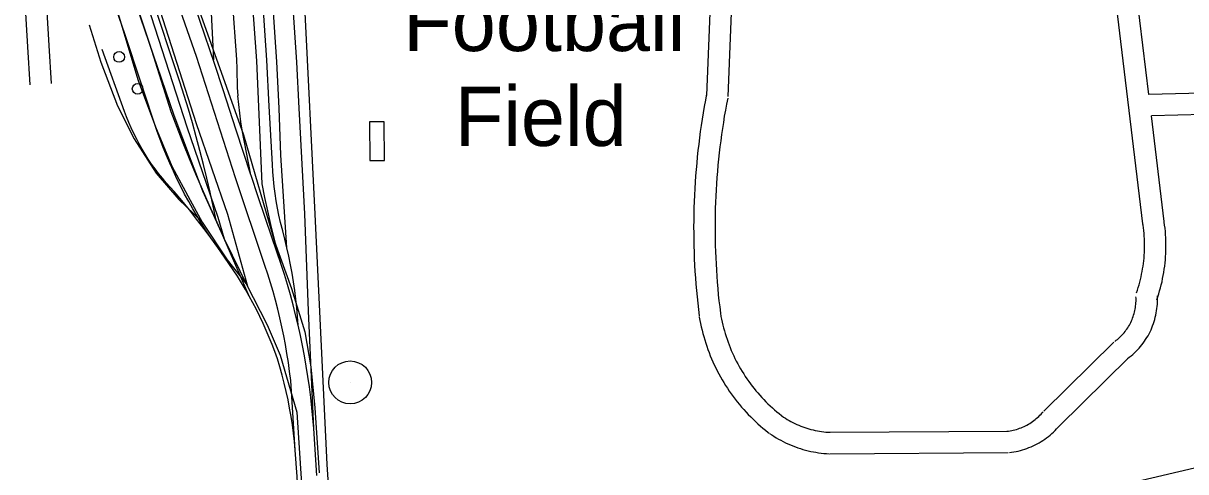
# Model space of a CAD drawing. Extents: x 3313447 to 3351316, y 703786 to 729172.
# Drawn here: x 3330404 to 3332031, y 712016 to 712643 of the extents above; entities that cross this region are included whole.
import ezdxf

# ---------------------------------------------------------------- set-up
doc = ezdxf.new("R2010")
doc.units = 0
for name, color, linetype in [('V-BLDG-IDEN', 7, 'Continuous'), ('V-BLDG-OTLN', 7, 'Continuous'), ('V-DOMW-TANK', 7, 'Continuous'), ('V-RAIL-TRAK', 7, 'Continuous'), ('V-ROAD-CNTR', 7, 'Continuous')]:
    doc.layers.add(name, color=color, linetype=linetype)

msp = doc.modelspace()

# ---------------------------------------------------------------- linework, layer by layer
at = {"layer": 'V-BLDG-OTLN'}
msp.add_lwpolyline([(3330908.9, 712505.4), (3330888.4, 712505.2), (3330888.9, 712451), (3330909.3, 712451.2)], close=True, dxfattribs=at)
at = {"layer": 'V-DOMW-TANK'}
msp.add_line((3330861.5, 712140.6), (3330861.5, 712140.6), dxfattribs=at)
for centre, radius in [((3330538, 712596.2), 7.6), ((3330563.9, 712551.5), 7.51), ((3330861.5, 712140.6), 30)]:
    msp.add_circle(centre, radius, dxfattribs=at)
at = {"layer": 'V-RAIL-TRAK'}
for p, q in [((3330738.2, 712418.4), (3330733.6, 712526.4)), ((3330752.7, 712445.7), (3330748, 712527.3)), ((3330751.8, 712344), (3330732.8, 712400.3)), ((3330720, 712261.5), (3330673.7, 712367.7)), ((3330764.9, 712305.5), (3330751.8, 712344)), ((3330769.4, 712291.5), (3330764.9, 712305.5)), ((3330810.6, 712076), (3330803, 712240.9))]:
    msp.add_line(p, q, dxfattribs=at)
for points in [[(3330555.1, 714786.3), (3330556.3, 714764.1), (3330562.7, 714620.4), (3330568.6, 714518.3), (3330575.8, 714388.5), (3330584.5, 714231), (3330594, 714085.6), (3330599, 713950), (3330607.6, 713814.8), (3330616.2, 713658.3), (3330624.9, 713507.5), (3330635.3, 713296.5), (3330670.1, 712592.1)], [(3330733.6, 712526.4), (3330730.6, 712590.9), (3330724.8, 712674), (3330720.4, 712758.3), (3330715.2, 712847.8), (3330709.8, 712944.5), (3330704.3, 713046.6), (3330700.3, 713123), (3330694.7, 713241.7)], [(3330748, 712527.3), (3330745, 712591.8), (3330739.2, 712674.9), (3330734.8, 712759.2), (3330729.6, 712848.7), (3330724.3, 712945.4), (3330718.8, 713047.5), (3330714.8, 713123.9), (3330709, 713238.6)], [(3330761.9, 712524.6), (3330758.9, 712589.1), (3330753.1, 712672.3), (3330748.7, 712756.5), (3330743.5, 712846), (3330738.2, 712942.7), (3330732.6, 713044.8), (3330728.7, 713121.2), (3330721.5, 713240.8)], [(3330789.9, 712524.5), (3330786.9, 712589), (3330781.1, 712672.1), (3330776.7, 712756.4), (3330771.6, 712845.9), (3330766.2, 712942.6), (3330760.7, 713044.7), (3330756.7, 713121.1), (3330750.5, 713241.7)], [(3330666.2, 713236.3), (3330672, 713124.8), (3330676, 713048.3), (3330681.5, 712946.3), (3330686.9, 712849.6), (3330692, 712760), (3330696.4, 712675.8), (3330702.2, 712592.7), (3330702.9, 712579.7)], [(3330673.7, 712367.7), (3330669.6, 712387.2), (3330665.3, 712406.8), (3330660.8, 712426.3), (3330656, 712445.7), (3330651.1, 712465.1), (3330645.9, 712484.4), (3330640.5, 712503.7), (3330634.9, 712522.9), (3330629.1, 712542.1), (3330623, 712561.1), (3330581.4, 712686.7), (3330537.1, 712816.2), (3330492.7, 712946.3), (3330429, 713159.4), (3330422.6, 713183.3)], [(3330673.7, 712367.7), (3330664, 712389), (3330654.5, 712410.4), (3330645.3, 712432), (3330636.3, 712453.6), (3330627.6, 712475.3), (3330619.1, 712497.2), (3330610.8, 712519.1), (3330581, 712613.9), (3330502.5, 712850.6), (3330464.1, 712962.8), (3330447.1, 713019.1), (3330441, 713043.5), (3330435.3, 713068), (3330429.8, 713092.5), (3330424.6, 713117.1)], [(3330666.5, 712342.8), (3330659.9, 712352.8), (3330653.5, 712362.9), (3330647.3, 712373.1), (3330641.2, 712383.4), (3330635.4, 712393.8), (3330629.7, 712404.3), (3330624.3, 712414.9), (3330619, 712425.6), (3330613.9, 712436.4), (3330609, 712447.3), (3330604.2, 712458.3), (3330599.7, 712469.3), (3330595.4, 712480.4), (3330591.3, 712491.6), (3330545.9, 712628.4), (3330474.3, 712836)], [(3330784.6, 712046), (3330778.2, 712143.2), (3330776.7, 712155.8), (3330774.9, 712168.4), (3330773, 712181), (3330770.9, 712193.5), (3330768.5, 712206), (3330765.9, 712218.5), (3330763.1, 712230.9), (3330760.2, 712243.3), (3330757, 712255.6), (3330753.6, 712267.9), (3330750, 712280.1), (3330746.1, 712292.2), (3330742.1, 712304.3), (3330701, 712427), (3330646.1, 712596.7), (3330576, 712798.2)], [(3330671.5, 712586.8), (3330651.5, 712645.7), (3330627.2, 712717)], [(3330691.7, 712307), (3330685.5, 712315.7), (3330676.1, 712329.4), (3330666.5, 712342.8), (3330656.6, 712356.1), (3330646.5, 712369.3), (3330636.3, 712382.3), (3330625.8, 712395.1), (3330615.1, 712407.8), (3330609.4, 712413.9), (3330603.9, 712420.1), (3330598.5, 712426.4), (3330593.3, 712432.9), (3330588.3, 712439.5), (3330583.5, 712446.3), (3330578.8, 712453.1), (3330574.3, 712460.1), (3330570.1, 712467.2), (3330566, 712474.5), (3330562.1, 712481.8), (3330558.4, 712489.2), (3330554.8, 712496.8), (3330551.5, 712504.4), (3330548.4, 712512.1), (3330545.5, 712519.9), (3330514.5, 712606.4)], [(3330701.9, 712493.8), (3330683.5, 712549.9), (3330671.5, 712586.8)], [(3330702.9, 712579.7), (3330703.4, 712553.6), (3330704.4, 712541.5)], [(3330722.3, 712431.1), (3330710.4, 712493.5), (3330708.6, 712505.5), (3330707, 712517.5), (3330705.6, 712529.5), (3330704.4, 712541.5)], [(3330773, 712329.1), (3330764.2, 712458.7), (3330761.9, 712524.6)], [(3330803, 712240.9), (3330798.2, 712376.5), (3330789.9, 712524.5)], [(3330732.8, 712400.3), (3330722.7, 712430), (3330722.3, 712431.1), (3330701.9, 712493.8)], [(3330773, 712329.1), (3330770.1, 712340.9), (3330767.1, 712352.7), (3330763.9, 712364.5), (3330761.7, 712374.5), (3330759.7, 712384.6), (3330758, 712394.7), (3330756.5, 712404.8), (3330755.2, 712415), (3330754.1, 712425.2), (3330753.3, 712435.5), (3330752.7, 712445.7)], [(3330764.9, 712305.5), (3330759.9, 712324.2), (3330755.2, 712342.9), (3330750.6, 712361.7), (3330746.3, 712380.6), (3330742.2, 712399.5), (3330738.2, 712418.4)], [(3330788.6, 712220.8), (3330787.7, 712232.9), (3330786.6, 712245.1), (3330785.3, 712257.2), (3330783.8, 712269.2), (3330782.1, 712281.3), (3330780.1, 712293.3), (3330778, 712305.3), (3330775.6, 712317.2), (3330773, 712329.1)], [(3330734.9, 712232.9), (3330730.1, 712242.5), (3330725.2, 712252), (3330720, 712261.5), (3330714.7, 712270.8), (3330709.2, 712280), (3330703.5, 712289.1), (3330697.7, 712298.1), (3330691.7, 712307)], [(3330791.7, 712206.5), (3330788.6, 712220.8), (3330785.1, 712235), (3330781.5, 712249.3), (3330777.7, 712263.4), (3330773.6, 712277.5), (3330769.4, 712291.5)], [(3330797.7, 711823.7), (3330787.4, 712008.8), (3330784.6, 712046), (3330783.5, 712057.8), (3330782.2, 712069.6), (3330780.6, 712081.3), (3330778.8, 712093), (3330776.7, 712104.7), (3330774.5, 712116.3), (3330772, 712127.9), (3330769.2, 712139.4), (3330766.3, 712150.9), (3330763.1, 712162.3), (3330759.7, 712173.6), (3330756, 712183.7), (3330752.2, 712193.7), (3330748.1, 712203.6), (3330743.9, 712213.5), (3330739.5, 712223.2), (3330734.9, 712232.9)], [(3330814.7, 712010.3), (3330810.6, 712076), (3330809.4, 712090.6), (3330808, 712105.2), (3330806.3, 712119.7), (3330804.4, 712134.3), (3330802.3, 712148.8), (3330800, 712163.3), (3330797.5, 712177.7), (3330794.7, 712192.1), (3330791.7, 712206.5)]]:
    msp.add_lwpolyline(points, dxfattribs=at)
at = {"layer": 'V-ROAD-CNTR'}
for points in [[(3328961.6, 713939.4), (3329039.1, 713944), (3329806.4, 713977.5), (3330187.4, 713991.9), (3330250.4, 713990.2), (3330279.9, 713978.3), (3330297.8, 713955.9), (3330309.3, 713931.9), (3330321, 713882.9), (3330330.7, 713794.2), (3330343.5, 713693.2), (3330351.1, 713553.5), (3330376.6, 713083.9), (3330398.6, 712799), (3330409.7, 712610.4), (3330412.9, 712557.2)], [(3330338.3, 713939.6), (3330350.6, 713888.1), (3330360.5, 713797.8), (3330373.4, 713695.9), (3330381.1, 713555.1), (3330406.6, 713085.8), (3330428.5, 712801), (3330439.6, 712612.2), (3330442.8, 712559)], [(3330399.4, 713532.9), (3330404.9, 713397.5), (3330507.1, 713072.5), (3330542.7, 712970.1), (3330565.3, 712902), (3330642.9, 712681.3), (3330712.1, 712487.2), (3330755.4, 712337.8), (3330779.2, 712272.1), (3330798, 712211.3), (3330806.2, 712162.3), (3330812.2, 712104.9), (3330818, 712014.2)], [(3330405.2, 713396.4), (3330415.6, 713266), (3330426.2, 713077.7), (3330425.1, 713014.3), (3330429.8, 712974.2), (3330441.5, 712929.6), (3330470.3, 712856.9), (3330509.5, 712747.1), (3330564.5, 712563.2), (3330589.1, 712498.2), (3330612, 712443.4), (3330637.5, 712395.9), (3330654.3, 712364.7), (3330689.4, 712312.3), (3330716, 712278.6), (3330745.3, 712221.2), (3330763.4, 712178.7), (3330786.9, 712098.9), (3330793.4, 711998.7)], [(3330718, 712274.7), (3330690, 712375.4), (3330646.5, 712502.4), (3330591.7, 712672.6), (3330541.3, 712818.2), (3330507.9, 712918.8), (3330479, 713010.3), (3330451.3, 713097.2), (3330419.6, 713195.3)], [(3330718.6, 712273.4), (3330685.6, 712341), (3330655.1, 712408.1), (3330639.3, 712449.9), (3330615.1, 712514.1), (3330562.1, 712668), (3330521.3, 712783.5), (3330477.2, 712914.6), (3330461.5, 712960.8), (3330421.9, 713153.6)], [(3330685.6, 712341), (3330676.6, 712371.3), (3330633.2, 712498), (3330578.4, 712668.1), (3330528, 712813.7), (3330494.6, 712914.5), (3330465.6, 713006.1), (3330438, 713092.9), (3330427.3, 713125.9)], [(3331971.1, 712362.4), (3331924.3, 712749.9)], [(3331979.4, 712543.6), (3331954.4, 712751)], [(3331367.5, 712727.6), (3331360.2, 712542.1)], [(3331397.6, 712729), (3331390.1, 712540.9)], [(3331031.2, 709188.4), (3331028.3, 709199.2), (3330994.2, 709307.7), (3330967.1, 709408.7), (3330951.4, 709492.8), (3330918.9, 710064), (3330884.7, 710683.2), (3330865.8, 711052.9), (3330850.4, 711373.9), (3330845.6, 711476.8), (3330839.8, 711570.4), (3330837.5, 711680.3), (3330841.4, 711753), (3330842.4, 711831.1), (3330829.2, 712025.5), (3330812.4, 712376), (3330798.1, 712667.2)], [(3330496, 712640.9), (3330512.6, 712589), (3330535.6, 712527.5), (3330558.9, 712481.4), (3330590, 712433.4), (3330621.6, 712396.4), (3330653.5, 712366.2)], [(3332259.6, 712555.3), (3332129.1, 712547.3), (3331979.4, 712543.6)], [(3331360.4, 712544.3), (3331358.8, 712535.6), (3331357.2, 712526.8), (3331355.7, 712518), (3331354.2, 712509.2), (3331352.9, 712500.4), (3331351.6, 712491.6), (3331350.4, 712482.8), (3331349.3, 712473.9), (3331348.3, 712465.1), (3331347.3, 712456.2), (3331346.5, 712447.4), (3331345.7, 712438.5), (3331345, 712429.6), (3331344.3, 712420.7), (3331343.8, 712411.8), (3331343.3, 712402.9), (3331343, 712394), (3331342.7, 712385.1), (3331342.4, 712376.2), (3331342.3, 712367.3), (3331342.2, 712358.4), (3331342.3, 712349.5), (3331342.4, 712340.5), (3331342.6, 712331.6), (3331342.8, 712322.7), (3331343.2, 712313.8), (3331343.6, 712304.9), (3331344.1, 712296), (3331344.7, 712287.1), (3331345.4, 712278.2), (3331346.1, 712269.4), (3331347, 712260.5), (3331347.9, 712251.6), (3331348.9, 712242.8), (3331350, 712234), (3331350.1, 712232.7)], [(3331389.9, 712538.6), (3331388.3, 712530.1), (3331386.7, 712521.6), (3331385.2, 712513.1), (3331383.9, 712504.6), (3331382.5, 712496), (3331381.3, 712487.5), (3331380.2, 712478.9), (3331379.1, 712470.3), (3331378.1, 712461.8), (3331377.2, 712453.2), (3331376.3, 712444.6), (3331375.6, 712436), (3331374.9, 712427.4), (3331374.3, 712418.7), (3331373.8, 712410.1), (3331373.3, 712401.5), (3331372.9, 712392.9), (3331372.6, 712384.2), (3331372.4, 712375.6), (3331372.3, 712367), (3331372.2, 712358.3), (3331372.3, 712349.7), (3331372.4, 712341), (3331372.6, 712332.4), (3331372.8, 712323.8), (3331373.2, 712315.1), (3331373.6, 712306.5), (3331374.1, 712297.9), (3331374.6, 712289.3), (3331375.3, 712280.7), (3331376, 712272), (3331376.8, 712263.4), (3331377.7, 712254.9), (3331378.7, 712246.3), (3331379.7, 712237.7), (3331379.9, 712236.5)], [(3332261.4, 712525.4), (3332130.4, 712517.3), (3331983, 712513.7)], [(3332000.8, 712366), (3331983, 712513.7)], [(3331962.2, 712266), (3331963.5, 712269.8), (3331964.7, 712273.4), (3331965.8, 712277.1), (3331966.8, 712280.8), (3331967.7, 712284.5), (3331968.6, 712288.2), (3331969.4, 712292), (3331970.2, 712295.7), (3331970.8, 712299.5), (3331971.4, 712303.3), (3331971.9, 712307.1), (3331972.4, 712310.9), (3331972.7, 712314.7), (3331973, 712318.6), (3331973.2, 712322.4), (3331973.4, 712326.2), (3331973.4, 712330.1), (3331973.4, 712333.9), (3331973.4, 712337.7), (3331973.2, 712341.6), (3331973, 712345.4), (3331972.7, 712349.2), (3331972.3, 712353), (3331971.9, 712356.8), (3331971.3, 712360.7), (3331971.1, 712362)], [(3331990.6, 712256.3), (3331992, 712260.4), (3331993.3, 712264.6), (3331994.6, 712268.8), (3331995.8, 712273.1), (3331996.9, 712277.3), (3331997.9, 712281.6), (3331998.8, 712286), (3331999.7, 712290.3), (3332000.4, 712294.6), (3332001.1, 712299), (3332001.7, 712303.4), (3332002.2, 712307.8), (3332002.6, 712312.2), (3332003, 712316.6), (3332003.2, 712321), (3332003.4, 712325.4), (3332003.4, 712329.8), (3332003.4, 712334.2), (3332003.4, 712338.6), (3332003.2, 712343.1), (3332002.9, 712347.5), (3332002.6, 712351.9), (3332002.1, 712356.3), (3332001.6, 712360.6), (3332001, 712365), (3332000.8, 712366.5)], [(3331949.8, 712174.1), (3331952.1, 712175.9), (3331954.5, 712177.8), (3331956.9, 712179.8), (3331959.2, 712181.9), (3331961.4, 712184), (3331963.6, 712186.2), (3331965.7, 712188.5), (3331967.7, 712190.8), (3331969.6, 712193.2), (3331971.5, 712195.7), (3331973.3, 712198.2), (3331975, 712200.8), (3331976.7, 712203.4), (3331978.3, 712206), (3331979.7, 712208.8), (3331981.1, 712211.5), (3331982.5, 712214.3), (3331983.7, 712217.1), (3331984.8, 712220), (3331985.9, 712222.9), (3331986.9, 712225.9), (3331987.8, 712228.8), (3331988.5, 712231.8), (3331989.2, 712234.8), (3331989.8, 712237.9), (3331990.4, 712240.9), (3331990.8, 712244), (3331991.1, 712247), (3331991.4, 712250.1), (3331991.5, 712253.2), (3331991.5, 712256.3), (3331991.5, 712259.4), (3331991.4, 712261.8)], [(3331931.8, 712198.1), (3331933.7, 712199.6), (3331935.4, 712200.9), (3331937.1, 712202.3), (3331938.7, 712203.8), (3331940.3, 712205.3), (3331941.8, 712206.9), (3331943.3, 712208.5), (3331944.7, 712210.1), (3331946.1, 712211.8), (3331947.4, 712213.6), (3331948.7, 712215.3), (3331949.9, 712217.1), (3331951.1, 712219), (3331952.2, 712220.9), (3331953.2, 712222.8), (3331954.2, 712224.7), (3331955.1, 712226.7), (3331956, 712228.7), (3331956.8, 712230.7), (3331957.6, 712232.8), (3331958.2, 712234.8), (3331958.9, 712236.9), (3331959.4, 712239), (3331959.9, 712241.2), (3331960.3, 712243.3), (3331960.7, 712245.5), (3331961, 712247.6), (3331961.2, 712249.8), (3331961.4, 712252), (3331961.5, 712254.2), (3331961.5, 712256.3), (3331961.5, 712258.5), (3331961.4, 712260.5)], [(3331350.2, 712232), (3331351, 712227.5), (3331352, 712222.9), (3331352.9, 712218.3), (3331354, 712213.7), (3331355.2, 712209.2), (3331356.4, 712204.7), (3331357.7, 712200.2), (3331359.1, 712195.7), (3331360.6, 712191.2), (3331362.2, 712186.8), (3331363.8, 712182.4), (3331365.5, 712178), (3331367.3, 712173.7), (3331369.2, 712169.4), (3331371.2, 712165.1), (3331373.2, 712160.9), (3331375.3, 712156.7), (3331377.5, 712152.6), (3331379.8, 712148.5), (3331382.1, 712144.4), (3331384.5, 712140.4), (3331387, 712136.4), (3331389.5, 712132.4), (3331392.2, 712128.5), (3331394.8, 712124.7), (3331397.6, 712120.9), (3331400.4, 712117.2), (3331403.3, 712113.5), (3331406.3, 712109.8), (3331409.3, 712106.2), (3331412.4, 712102.7), (3331415.6, 712099.2), (3331418.8, 712095.8), (3331422.1, 712092.5), (3331425.4, 712089.2), (3331428.8, 712085.9), (3331432.3, 712082.8), (3331435.8, 712079.6), (3331439.3, 712076.6), (3331443, 712073.6), (3331446.6, 712070.7), (3331447.8, 712069.8)], [(3331379.8, 712237.3), (3331380.5, 712233), (3331381.3, 712229), (3331382.2, 712224.9), (3331383.2, 712220.9), (3331384.2, 712216.8), (3331385.3, 712212.8), (3331386.4, 712208.9), (3331387.7, 712204.9), (3331389, 712201), (3331390.4, 712197.1), (3331391.8, 712193.2), (3331393.4, 712189.3), (3331394.9, 712185.5), (3331396.6, 712181.7), (3331398.3, 712177.9), (3331400.1, 712174.2), (3331402, 712170.4), (3331403.9, 712166.8), (3331405.9, 712163.1), (3331408, 712159.5), (3331410.1, 712156), (3331412.3, 712152.5), (3331414.6, 712149), (3331416.9, 712145.5), (3331419.3, 712142.1), (3331421.7, 712138.8), (3331424.2, 712135.5), (3331426.8, 712132.2), (3331429.4, 712129), (3331432.1, 712125.8), (3331434.8, 712122.7), (3331437.6, 712119.6), (3331440.4, 712116.6), (3331443.3, 712113.6), (3331446.3, 712110.7), (3331449.3, 712107.8), (3331452.4, 712105), (3331455.5, 712102.3), (3331458.6, 712099.6), (3331461.8, 712097), (3331465.1, 712094.3), (3331466.2, 712093.5)], [(3331832.3, 712100.5), (3331930.3, 712196.8)], [(3331853.4, 712079.1), (3331951.3, 712175.4)], [(3331780.6, 712072.2), (3331783, 712072.5), (3331785.3, 712072.9), (3331787.5, 712073.3), (3331789.7, 712073.8), (3331791.9, 712074.3), (3331794.1, 712074.9), (3331796.3, 712075.6), (3331798.5, 712076.4), (3331800.6, 712077.2), (3331802.7, 712078), (3331804.8, 712079), (3331806.8, 712080), (3331808.8, 712081), (3331810.8, 712082.1), (3331812.7, 712083.3), (3331814.7, 712084.5), (3331816.5, 712085.8), (3331818.4, 712087.1), (3331820.2, 712088.5), (3331821.9, 712090), (3331823.6, 712091.4), (3331825.3, 712093), (3331826.9, 712094.6), (3331828.5, 712096.2), (3331830, 712097.9), (3331831.5, 712099.6)], [(3331465.5, 712094), (3331468.2, 712092.2), (3331470.7, 712090.5), (3331473.3, 712088.9), (3331475.9, 712087.4), (3331478.5, 712086), (3331481.2, 712084.6), (3331483.9, 712083.2), (3331486.6, 712081.9), (3331489.4, 712080.7), (3331492.2, 712079.6), (3331495, 712078.5), (3331497.9, 712077.5), (3331500.7, 712076.6), (3331503.6, 712075.7), (3331506.5, 712074.9), (3331509.5, 712074.1), (3331512.4, 712073.5), (3331515.4, 712072.9), (3331518.3, 712072.4), (3331521.3, 712071.9), (3331524.3, 712071.5), (3331527.3, 712071.2), (3331530.3, 712071), (3331533.4, 712070.8), (3331533.4, 712070.8)], [(3332319.9, 712090.7), (3332291.8, 712083.9), (3332150.8, 712046), (3331938.1, 711995.8)], [(3331448.5, 712069.3), (3331451.5, 712067.3), (3331454.6, 712065.2), (3331457.8, 712063.2), (3331461, 712061.4), (3331464.3, 712059.6), (3331467.6, 712057.8), (3331470.9, 712056.2), (3331474.3, 712054.6), (3331477.7, 712053.1), (3331481.2, 712051.7), (3331484.6, 712050.4), (3331488.2, 712049.1), (3331491.7, 712047.9), (3331495.3, 712046.9), (3331498.9, 712045.9), (3331502.5, 712045), (3331506.1, 712044.1), (3331509.8, 712043.4), (3331513.5, 712042.8), (3331517.2, 712042.2), (3331520.9, 712041.7), (3331524.6, 712041.3), (3331528.3, 712041), (3331531.9, 712040.8), (3331532.1, 712040.8)], [(3331532.7, 712070.8), (3331782.4, 712072.3)], [(3331784.4, 712042.4), (3331787.3, 712042.8), (3331790.4, 712043.3), (3331793.5, 712043.9), (3331796.6, 712044.6), (3331799.6, 712045.3), (3331802.7, 712046.2), (3331805.7, 712047.1), (3331808.7, 712048.2), (3331811.6, 712049.3), (3331814.5, 712050.5), (3331817.4, 712051.8), (3331820.3, 712053.1), (3331823.1, 712054.6), (3331825.8, 712056.1), (3331828.5, 712057.8), (3331831.2, 712059.5), (3331833.8, 712061.2), (3331836.4, 712063.1), (3331838.9, 712065), (3331841.3, 712067), (3331843.7, 712069.1), (3331846, 712071.2), (3331848.2, 712073.5), (3331850.4, 712075.7), (3331852.5, 712078.1), (3331854.2, 712080)], [(3331532.9, 712040.8), (3331782.6, 712042.3)]]:
    msp.add_lwpolyline(points, dxfattribs=at)

# ---------------------------------------------------------------- texts
at = {"layer": 'V-BLDG-IDEN'}
for s, p in [('Football', (3330935.8, 712604.4)), ('Field', (3331008, 712471.6))]:
    msp.add_text(s, height=83, dxfattribs=at).set_placement(p)

doc.saveas('drawing.dxf')
